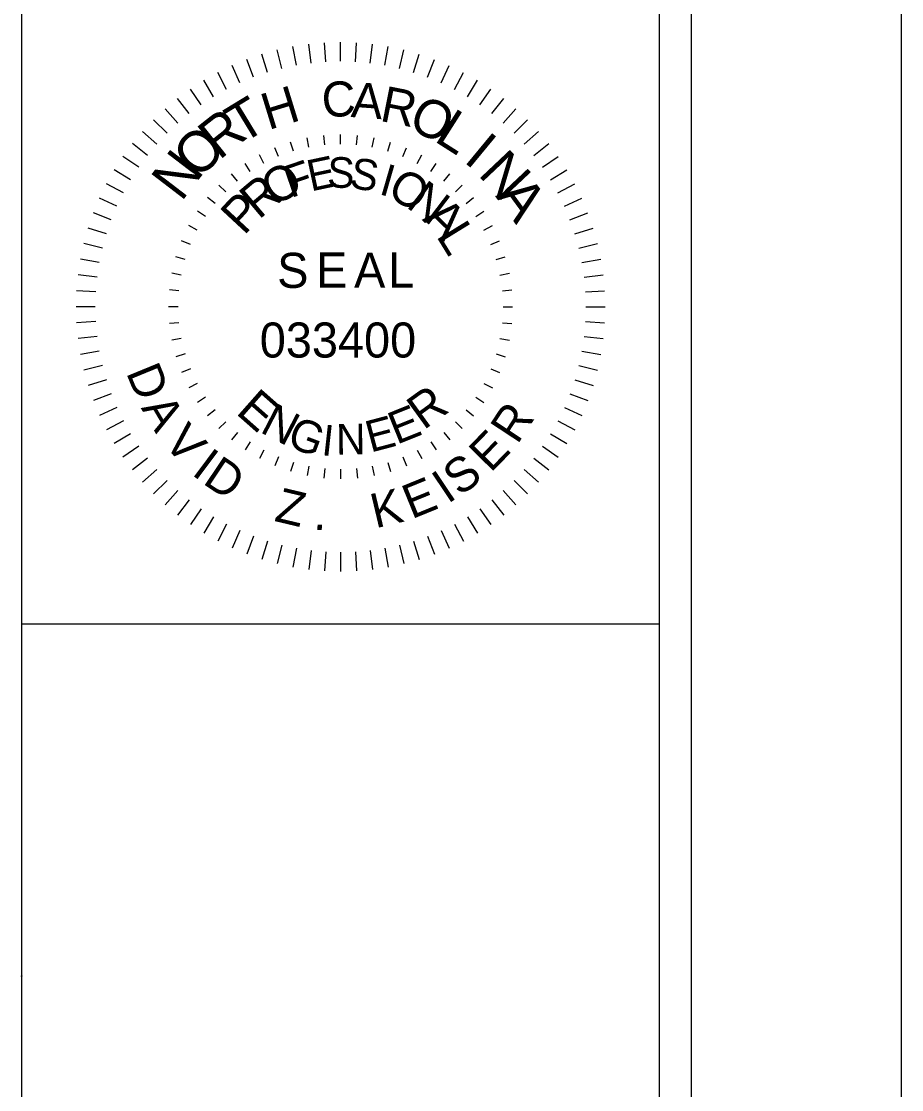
# Model space of a CAD drawing. Extents: x -63 to 3072, y 0 to 1100.
# Drawn here: x 1561.9 to 1700, y 773.6 to 941 of the extents above; entities that cross this region are included whole.
import ezdxf

# ---------------------------------------------------------------- set-up
doc = ezdxf.new("R2010")
doc.units = 0
for name, color, linetype in [('PROP SAN SEWER', 7, 'Continuous'), ('Scratch_Level_0', 7, 'Continuous'), ('Sheet Plan CELL', 7, 'Continuous'), ('Sheet_Plan_CELL', 7, 'Continuous'), ('Sheet_RDY_PE_Seal_Cell', 7, 'Continuous')]:
    doc.layers.add(name, color=color, linetype=linetype)

msp = doc.modelspace()

# ---------------------------------------------------------------- linework, layer by layer
at = {"layer": 'PROP SAN SEWER'}
for p, q in [((1602.79, 933.67), (1602.07, 936.58)), ((1605.06, 934.16), (1604.52, 937.11)), ((1607.36, 934.51), (1607, 937.48)), ((1609.67, 934.72), (1609.49, 937.71)), ((1612, 934.79), (1612, 937.79)), ((1614.32, 934.72), (1614.5, 937.71)), ((1616.64, 934.51), (1617, 937.48)), ((1618.93, 934.16), (1619.48, 937.11)), ((1621.21, 933.67), (1621.92, 936.58)), ((1598.35, 932.29), (1597.29, 935.09)), ((1600.55, 933.04), (1599.66, 935.91)), ((1623.44, 933.04), (1624.34, 935.91)), ((1625.64, 932.29), (1626.71, 935.09)), ((1594.12, 930.38), (1592.72, 933.03)), ((1596.21, 931.4), (1594.98, 934.13)), ((1627.79, 931.4), (1629.02, 934.13)), ((1629.88, 930.38), (1631.27, 933.03)), ((1592.09, 929.24), (1590.54, 931.81)), ((1631.9, 929.24), (1633.45, 931.81)), ((1590.14, 927.98), (1588.44, 930.44)), ((1633.85, 927.98), (1635.56, 930.44)), ((1588.27, 926.6), (1586.42, 928.96)), ((1635.73, 926.6), (1637.58, 928.96)), ((1586.48, 925.11), (1584.49, 927.35)), ((1637.51, 925.11), (1639.5, 927.36)), ((1584.79, 923.52), (1582.67, 925.64)), ((1639.21, 923.52), (1641.32, 925.64)), ((1583.2, 921.82), (1580.95, 923.81)), ((1607.03, 921.31), (1606.73, 922.78)), ((1609.5, 921.67), (1609.35, 923.16)), ((1612, 921.8), (1612, 923.29)), ((1614.5, 921.67), (1614.64, 923.16)), ((1616.97, 921.31), (1617.26, 922.78)), ((1640.8, 921.82), (1643.04, 923.81)), ((1581.71, 920.04), (1579.35, 921.89)), ((1602.25, 919.85), (1601.67, 921.24)), ((1604.6, 920.7), (1604.16, 922.13)), ((1619.39, 920.7), (1619.83, 922.13)), ((1621.75, 919.85), (1622.33, 921.24)), ((1642.29, 920.04), (1644.65, 921.89)), ((1580.33, 918.17), (1577.87, 919.87)), ((1599.98, 918.79), (1599.28, 920.11)), ((1624.01, 918.79), (1624.72, 920.11)), ((1643.66, 918.17), (1646.13, 919.87)), ((1579.07, 916.22), (1576.5, 917.77)), ((1597.84, 917.5), (1597.01, 918.75)), ((1626.16, 917.5), (1626.99, 918.75)), ((1644.93, 916.22), (1647.49, 917.77)), ((1595.83, 916.01), (1594.88, 917.17)), ((1628.17, 916.01), (1629.12, 917.17)), ((1577.93, 914.19), (1575.27, 915.58)), ((1593.98, 914.33), (1592.92, 915.39)), ((1630.02, 914.33), (1631.08, 915.39)), ((1646.07, 914.19), (1648.72, 915.59)), ((1576.91, 912.1), (1574.18, 913.33)), ((1592.3, 912.48), (1591.14, 913.43)), ((1631.7, 912.48), (1632.86, 913.43)), ((1647.09, 912.1), (1649.82, 913.33)), ((1576.02, 909.95), (1573.22, 911.02)), ((1590.81, 910.47), (1589.56, 911.3)), ((1633.19, 910.47), (1634.44, 911.3)), ((1647.97, 909.95), (1650.78, 911.02)), ((1575.26, 907.76), (1572.4, 908.65)), ((1589.52, 908.32), (1588.2, 909.03)), ((1634.47, 908.32), (1635.8, 909.03)), ((1648.74, 907.76), (1651.59, 908.65)), ((1574.64, 905.52), (1571.73, 906.24)), ((1588.45, 906.06), (1587.07, 906.63)), ((1635.54, 906.06), (1636.93, 906.63)), ((1649.36, 905.52), (1652.27, 906.24)), ((1574.15, 903.25), (1571.2, 903.79)), ((1587.61, 903.71), (1586.17, 904.14)), ((1636.38, 903.71), (1637.82, 904.14)), ((1649.84, 903.25), (1652.8, 903.79)), ((1573.8, 900.95), (1570.82, 901.31)), ((1587, 901.28), (1585.53, 901.57)), ((1636.99, 901.28), (1638.46, 901.57)), ((1650.19, 900.95), (1653.17, 901.31)), ((1573.59, 898.63), (1570.6, 898.81)), ((1586.64, 898.81), (1585.14, 898.95)), ((1637.36, 898.81), (1638.85, 898.95)), ((1650.41, 898.63), (1653.4, 898.81)), ((1573.52, 896.31), (1570.52, 896.31)), ((1586.51, 896.31), (1585.01, 896.31)), ((1637.48, 896.31), (1638.98, 896.31)), ((1650.48, 896.31), (1653.47, 896.31)), ((1573.59, 893.99), (1570.6, 893.81)), ((1586.64, 893.81), (1585.14, 893.67)), ((1637.36, 893.81), (1638.85, 893.67)), ((1650.41, 893.99), (1653.4, 893.81)), ((1573.8, 891.67), (1570.82, 891.31)), ((1587, 891.34), (1585.53, 891.05)), ((1636.99, 891.34), (1638.46, 891.05)), ((1650.19, 891.67), (1653.17, 891.31)), ((1574.15, 889.37), (1571.2, 888.83)), ((1649.84, 889.37), (1652.79, 888.83)), ((1587.61, 888.91), (1586.17, 888.48)), ((1636.38, 888.91), (1637.82, 888.48)), ((1574.64, 887.1), (1571.73, 886.38)), ((1588.45, 886.56), (1587.07, 885.98)), ((1635.54, 886.56), (1636.93, 885.98)), ((1649.36, 887.1), (1652.27, 886.38)), ((1575.26, 884.86), (1572.4, 883.97)), ((1589.52, 884.3), (1588.2, 883.59)), ((1634.47, 884.3), (1635.8, 883.59)), ((1648.74, 884.86), (1651.59, 883.97)), ((1576.02, 882.66), (1573.22, 881.6)), ((1647.97, 882.66), (1650.78, 881.6)), ((1590.81, 882.15), (1589.56, 881.32)), ((1633.19, 882.15), (1634.44, 881.32)), ((1576.91, 880.52), (1574.18, 879.29)), ((1592.3, 880.14), (1591.14, 879.19)), ((1631.7, 880.14), (1632.86, 879.19)), ((1647.09, 880.52), (1649.82, 879.29)), ((1577.93, 878.43), (1575.27, 877.04)), ((1593.98, 878.29), (1592.92, 877.23)), ((1630.02, 878.29), (1631.08, 877.23)), ((1646.07, 878.43), (1648.72, 877.04)), ((1579.07, 876.4), (1576.5, 874.85)), ((1595.83, 876.61), (1594.88, 875.45)), ((1628.17, 876.61), (1629.12, 875.45)), ((1644.93, 876.4), (1647.49, 874.85)), ((1580.33, 874.45), (1577.87, 872.75)), ((1597.84, 875.12), (1597.01, 873.87)), ((1626.16, 875.12), (1626.99, 873.87)), ((1643.66, 874.45), (1646.13, 872.75)), ((1581.71, 872.58), (1579.35, 870.73)), ((1599.98, 873.83), (1599.28, 872.51)), ((1602.25, 872.76), (1601.67, 871.38)), ((1621.75, 872.76), (1622.33, 871.38)), ((1624.01, 873.83), (1624.72, 872.51)), ((1642.29, 872.58), (1644.65, 870.73)), ((1604.6, 871.92), (1604.16, 870.49)), ((1607.03, 871.32), (1606.73, 869.84)), ((1609.5, 870.95), (1609.35, 869.46)), ((1612, 870.83), (1612, 869.33)), ((1614.5, 870.95), (1614.64, 869.46)), ((1616.97, 871.31), (1617.26, 869.84)), ((1619.39, 871.92), (1619.83, 870.49)), ((1583.2, 870.8), (1580.95, 868.81)), ((1640.8, 870.8), (1643.04, 868.81)), ((1584.79, 869.1), (1582.67, 866.98)), ((1586.48, 867.51), (1584.49, 865.27)), ((1637.51, 867.51), (1639.5, 865.27)), ((1639.21, 869.1), (1641.32, 866.98)), ((1588.27, 866.02), (1586.42, 863.66)), ((1635.73, 866.02), (1637.58, 863.66)), ((1590.14, 864.64), (1588.44, 862.18)), ((1633.85, 864.64), (1635.56, 862.18)), ((1592.09, 863.38), (1590.54, 860.82)), ((1631.9, 863.38), (1633.45, 860.82)), ((1594.12, 862.24), (1592.72, 859.58)), ((1596.21, 861.22), (1594.98, 858.49)), ((1627.79, 861.22), (1629.02, 858.49)), ((1629.88, 862.24), (1631.27, 859.58)), ((1598.35, 860.33), (1597.29, 857.53)), ((1600.55, 859.57), (1599.66, 856.71)), ((1623.44, 859.57), (1624.34, 856.71)), ((1625.64, 860.33), (1626.71, 857.53)), ((1602.79, 858.95), (1602.07, 856.04)), ((1605.06, 858.46), (1604.52, 855.51)), ((1607.36, 858.11), (1607, 855.14)), ((1609.67, 857.9), (1609.49, 854.91)), ((1612, 857.83), (1612, 854.83)), ((1614.32, 857.9), (1614.5, 854.91)), ((1616.64, 858.11), (1617, 855.14)), ((1618.93, 858.46), (1619.48, 855.51)), ((1621.21, 858.95), (1621.92, 856.04))]:
    msp.add_line(p, q, dxfattribs=at)
at = {"layer": 'Scratch_Level_0'}
msp.add_line((1699.98, 0), (1699.98, 1100), dxfattribs=at)
at = {"layer": 'Sheet Plan CELL'}
msp.add_circle((1561.99, 791.38), 0.0603, dxfattribs=at)
at = {"layer": 'Sheet_Plan_CELL'}
msp.add_line((1661.97, 846.56), (1561.97, 846.56), dxfattribs=at)
at = {"layer": 'Sheet_RDY_PE_Seal_Cell'}
for p, q in [((1561.97, 39.96), (1562, 1059.93)), ((1662, 39.96), (1662, 1059.91)), ((1667, 39.99), (1667, 1059.91))]:
    msp.add_line(p, q, dxfattribs=at)

# ---------------------------------------------------------------- texts
at = {"layer": 'PROP SAN SEWER'}
for s, height, rotation, p in [('C', 5.5, 2.964, (1609.17, 925.99)), ('A', 5.51, 355.8747, (1613.53, 926.06)), ('T', 6.13, 31.3209, (1596.48, 921.73)), ('H', 5.73, 17.1424, (1600.66, 923.98)), ('R', 5.6, 348.7855, (1617.99, 925.48)), ('O', 5.96, 334.607, (1622.35, 924.36)), ('R', 6.3, 38.4101, (1592.94, 919.2)), ('L', 6.16, 327.5178, (1626.5, 922.38)), ('O', 6.4, 45.4993, (1589.69, 916.1)), ('I', 6.32, 320.4286, (1631.13, 919.14)), ('N', 6.4, 52.5886, (1587.01, 912.65)), ('E', 4.9, 11.9657, (1607.32, 914.37)), ('S', 4.8, 357.9015, (1609.83, 915.04)), ('S', 4.86, 350.8694, (1613.25, 914.99)), ('N', 6.41, 313.3394, (1633.4, 917.02)), ('O', 5.39, 33.0621, (1601.8, 911.92)), ('F', 5.04, 18.9979, (1604.16, 913.33)), ('I', 4.98, 343.8373, (1617.85, 914.02)), ('R', 5.53, 40.0942, (1599.16, 909.87)), ('O', 5.32, 329.773, (1619.07, 913.77)), ('N', 5.48, 322.7409, (1622.1, 912.05)), ('A', 6.39, 306.2501, (1636.19, 913.68)), ('P', 5.6, 47.1264, (1596.83, 907.37)), ('A', 5.58, 315.7088, (1624.7, 909.96)), ('L', 5.51, 301.6445, (1626.9, 907.45)), ('S', 5.5, 0, (1602.05, 899.27)), ('E', 5.5, 0, (1608.15, 899.32)), ('A', 5.5, 0, (1614.11, 899.3)), ('L', 5.5, 0, (1619.43, 899.32)), ('033400', 5.497, 0, (1599.32, 888.35)), ('D', 5.4, 292.3254, (1578.31, 886.02)), ('E', 5.55, 318.5439, (1595.41, 879.65)), ('R', 5.45, 35.8972, (1625.02, 876.9)), ('A', 5.4, 300.5566, (1580.64, 880.44)), ('N', 5.25, 332.6082, (1599.18, 876.73)), ('E', 5.11, 21.833, (1620.79, 874.66)), ('R', 5.4, 56.6621, (1639.7, 874.6)), ('E', 4.95, 14.8009, (1616.69, 873.43)), ('V', 5.4, 311.7772, (1584.07, 874.92)), ('G', 5.07, 339.6403, (1603.37, 874.51)), ('I', 4.83, 353.7045, (1608.88, 873.07)), ('N', 4.8, 0.7366, (1611.3, 873.13)), ('E', 5.4, 45.3772, (1635.5, 870.19)), ('I', 5.4, 323.2372, (1588.48, 870.1)), ('D', 5.4, 326.1338, (1590.2, 868.69)), ('S', 5.4, 36.7617, (1630.68, 866.49)), ('E', 5.4, 22.1784, (1623.13, 862.97)), ('I', 5.4, 33.8651, (1628.78, 865.33)), ('Z', 5.4, 346.6654, (1601.46, 862.76)), ('K', 5.4, 13.3335, (1617.45, 861.56)), ('.', 5.4, 358.5162, (1607.7, 861.33))]:
    msp.add_text(s, height=height, rotation=rotation, dxfattribs=at).set_placement(p)

doc.saveas('drawing.dxf')
